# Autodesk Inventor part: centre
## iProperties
Shininess: 64.0
Length Units: 11269
Angle Units: 11279
Time Units: 11290
Mass Units: 11283
Length Display Precision: 3
Angle Display Precision: 2
Compacted: True
Part Number: centre
Document SubType Name: Modeling
Created: 2004-10
Material: Standard
Designer: W. Holzwarth
Manufacturer: Standard
Standards Organization: Custom
Density: 0.0
Volumn: 0.0
Area: 0.0
PropertySet Name: Model Information
Control State: 0
Master: False
Checked Out: False
Author: W. Holzwarth
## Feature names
1. Basis1
